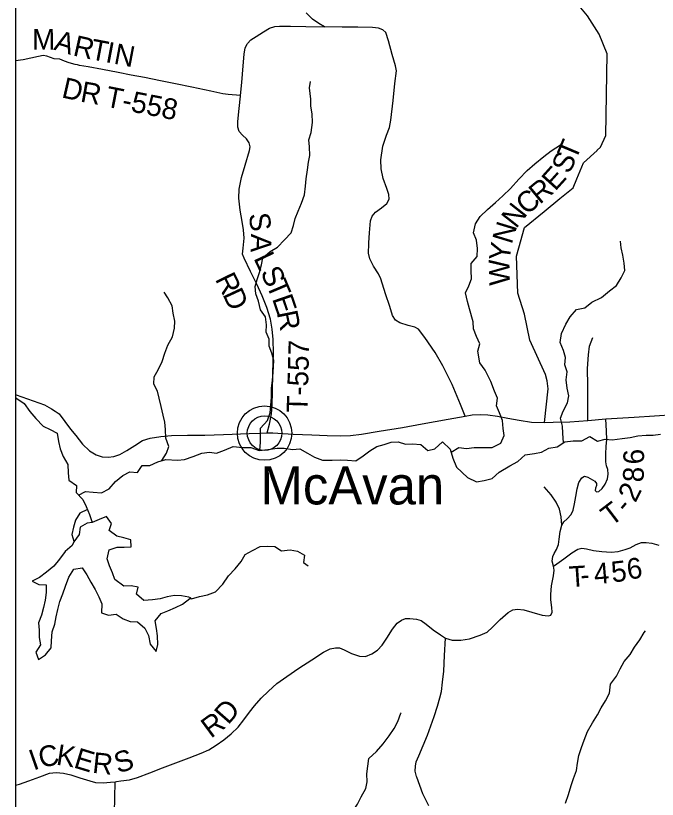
# Model space of a CAD drawing. Extents: x -84548 to 2262448, y -162180 to 525962.
# Drawn here: x 31945 to 41232, y 148023 to 159360 of the extents above; entities that cross this region are included whole.
import ezdxf

# ---------------------------------------------------------------- set-up
doc = ezdxf.new("R2010")
doc.units = 0
for name, color, linetype in [('GM_X_Adjacent_County_Text', 7, 'Continuous'), ('GM_X_County', 7, 'Continuous'), ('GM_X_Interchange_Ramps', 7, 'Continuous'), ('GM_X_Major_Lake_Text', 7, 'Continuous'), ('GM_X_Major_River', 7, 'Continuous'), ('GM_X_Minor_Lake', 7, 'Continuous'), ('GM_X_Minor_River_Text', 7, 'Continuous'), ('GM_X_State_Route', 7, 'Continuous'), ('GM_X_Township_Road', 7, 'Continuous'), ('GM_X_Township_ROW', 7, 'Continuous')]:
    doc.layers.add(name, color=color, linetype=linetype)

msp = doc.modelspace()

# ---------------------------------------------------------------- linework, layer by layer
at = {"layer": 'GM_X_County'}
msp.add_line((31945, 170872), (31945, 134968), dxfattribs=at)
at = {"layer": 'GM_X_Interchange_Ramps'}
for points in [[(34474, 150936), (34450, 150948), (34347, 150966), (34243, 150970), (34136, 150952), (34036, 150922), (33925, 150910), (33799, 150900), (33692, 150992), (33716, 151092), (33616, 151112), (33511, 151106), (33381, 151201), (33348, 151301), (33302, 151403), (33268, 151503), (33298, 151632), (33413, 151670), (33517, 151670), (33618, 151676), (33612, 151778), (33511, 151806), (33411, 151830), (33300, 151910), (33334, 152012), (33260, 152113), (33155, 152069), (33051, 152029)], [(33051, 152029), (32978, 152018), (32878, 151958), (32866, 151852), (32789, 151750)], [(32789, 151750), (32761, 151694), (32661, 151608), (32580, 151499), (32498, 151395), (32393, 151311), (32289, 151233), (32182, 151179), (32283, 151132), (32387, 151124), (32389, 151014), (32371, 150904), (32349, 150800), (32321, 150685), (32277, 150575), (32287, 150469), (32285, 150365), (32303, 150260), (32239, 150150), (32277, 150048), (32377, 150112), (32458, 150212), (32462, 150317), (32476, 150445), (32510, 150557), (32530, 150663), (32556, 150768), (32586, 150884), (32629, 150996), (32667, 151106), (32715, 151239), (32789, 151351), (32908, 151371), (32974, 151271), (33035, 151165), (33097, 151060), (33151, 150952), (33192, 150852), (33186, 150721), (33290, 150685), (33399, 150701), (33501, 150635), (33602, 150595), (33708, 150589), (33817, 150499), (33869, 150393), (33893, 150268), (33980, 150162), (34002, 150262), (33998, 150387), (33984, 150495), (33962, 150603), (34050, 150710), (34150, 150752), (34259, 150798), (34360, 150844), (34466, 150928)], [(34466, 150928), (34490, 150924)], [(34490, 150924), (34474, 150936)]]:
    msp.add_lwpolyline(points, dxfattribs=at)
at = {"layer": 'GM_X_Major_Lake_Text'}
for points in [[(31945, 153877), (31954, 153874), (32362, 153729), (32462, 153674), (32519, 153636), (32573, 153598), (32656, 153489)], [(35326, 153316), (35494, 153322), (35585, 153323), (35668, 153325), (35962, 153307), (36232, 153294), (36454, 153284), (36647, 153279), (36791, 153286), (36951, 153305), (37207, 153347), (37546, 153403), (37830, 153453), (38203, 153523), (38452, 153567), (38552, 153583), (38672, 153592), (38778, 153585), (38920, 153566), (39068, 153539), (39234, 153506), (39410, 153479), (39598, 153475), (39726, 153479), (39968, 153486), (40225, 153503), (40489, 153525), (40899, 153552), (41192, 153570), (41476, 153592)], [(32656, 153489), (32740, 153378), (32814, 153285), (32911, 153163), (33013, 153065), (33110, 153006), (33198, 152979), (33284, 152973), (33366, 152984), (33455, 153012), (33555, 153069), (33668, 153142), (33780, 153213), (33892, 153249), (34045, 153272), (34201, 153285), (34433, 153289), (34683, 153293), (34951, 153302), (35326, 153316)]]:
    msp.add_lwpolyline(points, dxfattribs=at)
at = {"layer": 'GM_X_Major_River'}
for radius in [393, 249]:
    msp.add_circle((35547, 153320), radius, dxfattribs=at)
at = {"layer": 'GM_X_Minor_Lake'}
for points in [[(40363, 157412), (40411, 157457), (40487, 157628), (40506, 158807), (40392, 159092), (40221, 159358), (40126, 159472), (40069, 159529), (40031, 159605), (40069, 159700), (40031, 159852), (39917, 160042), (39936, 160708), (39986, 161675), (39986, 161676)], [(35298, 158950), (35302, 158958), (35349, 159011), (35426, 159060), (35532, 159128), (35619, 159178), (35695, 159204), (35765, 159209), (35923, 159206), (36145, 159203), (36413, 159196)], [(35585, 153323), (35619, 153449), (35646, 153600), (35657, 153730), (35661, 153913), (35669, 154199), (35676, 154480), (35673, 154676), (35660, 154824), (35633, 154970), (35582, 155139), (35513, 155308), (35437, 155475), (35346, 155657), (35252, 155854), (35230, 155909), (35239, 155994), (35252, 156142), (35245, 156260), (35223, 156382), (35195, 156548), (35176, 156722), (35179, 156850), (35216, 157017), (35268, 157196), (35332, 157410), (35339, 157462), (35324, 157518), (35284, 157579), (35229, 157630), (35180, 157685), (35159, 157745), (35161, 157827), (35181, 158016), (35200, 158196), (35201, 158206), (35218, 158395), (35239, 158632), (35253, 158804), (35269, 158893), (35297, 158948), (35298, 158950)], [(32870, 158641), (32841, 158647), (32805, 158653), (32721, 158676), (32654, 158704), (32584, 158729), (32504, 158737), (32450, 158754), (32397, 158773), (32345, 158782), (32275, 158767), (32052, 158720), (31945, 158707)], [(35201, 158206), (35023, 158219), (34945, 158229), (34772, 158268), (34493, 158324), (34259, 158372), (34042, 158416), (33809, 158463), (33618, 158499), (33430, 158536), (33201, 158579), (32994, 158619), (32870, 158641)], [(39227, 155999), (39228, 156000), (39309, 156297), (39594, 156526), (39822, 156716), (40012, 156868), (40069, 157001), (40164, 157229), (40362, 157411), (40363, 157412)], [(39598, 153475), (39651, 153959), (39638, 154079), (39613, 154168), (39385, 154663), (39309, 155043), (39214, 155347), (39195, 155879), (39227, 155999)], [(39729, 151395), (39711, 151467), (39720, 151538), (39737, 151580), (39774, 151635), (39802, 151709), (39813, 151788), (39826, 151896), (39852, 151988), (39879, 152038), (39929, 152081), (39983, 152142), (40012, 152204), (40034, 152297), (40054, 152406), (40074, 152516), (40098, 152607), (40140, 152676), (40178, 152697), (40228, 152684), (40327, 152627), (40354, 152594), (40354, 152564), (40335, 152525), (40334, 152489), (40352, 152470), (40384, 152476), (40433, 152519), (40478, 152582), (40512, 152657), (40519, 152727), (40518, 152793), (40497, 152847), (40485, 152905), (40489, 153019), (40491, 153129), (40501, 153226), (40496, 153348), (40489, 153525)], [(39852, 151988), (39838, 152111), (39816, 152221), (39766, 152320), (39696, 152427), (39595, 152543)], [(39729, 151396), (39742, 151405), (39878, 151503), (39997, 151589), (40083, 151643), (40139, 151654), (40207, 151647), (40308, 151621), (40428, 151606), (40562, 151600), (40666, 151610), (40769, 151635), (40841, 151660), (40926, 151710), (41001, 151737), (41071, 151739), (41153, 151728), (41254, 151698)], [(31945, 148230), (32003, 148242), (32136, 148289), (32297, 148350), (32433, 148399), (32533, 148413), (32639, 148401), (32744, 148375), (32875, 148332), (33017, 148291), (33100, 148268), (33212, 148263), (33320, 148269), (33385, 148277), (33404, 148280), (33467, 148288), (33595, 148306), (33710, 148337), (33885, 148406), (34071, 148476), (34262, 148552), (34456, 148624), (34631, 148690), (34739, 148740), (34846, 148806), (34956, 148882), (35063, 148971), (35167, 149067), (35248, 149171), (35330, 149285), (35400, 149376), (35498, 149484), (35606, 149587), (35727, 149699), (35869, 149798), (36043, 149920), (36230, 150042), (36400, 150153), (36499, 150199), (36574, 150213), (36634, 150212), (36699, 150187), (36808, 150133), (36923, 150092), (37007, 150087), (37100, 150127), (37181, 150181), (37251, 150254), (37319, 150354), (37398, 150484), (37469, 150573), (37530, 150617), (37587, 150638), (37651, 150639), (37745, 150629), (37814, 150608), (37885, 150558), (37990, 150477), (38094, 150401), (38165, 150353), (38263, 150325), (38389, 150323), (38513, 150346), (38670, 150397), (38771, 150441), (38847, 150513), (38959, 150623), (39071, 150727), (39140, 150765), (39210, 150776), (39302, 150762), (39416, 150730), (39567, 150687), (39651, 150675), (39689, 150686), (39708, 150728), (39707, 150798), (39693, 150910), (39689, 150986), (39702, 151113), (39728, 151255), (39740, 151338), (39729, 151395), (39729, 151396)], [(37749, 148353), (37728, 148431), (37731, 148501), (37744, 148563), (37780, 148652), (37841, 148800), (37908, 148953), (37953, 149084), (38002, 149222), (38051, 149369), (38084, 149490), (38107, 149582), (38124, 149717), (38141, 149877), (38150, 150104), (38165, 150353)], [(37927, 147927), (37840, 148101), (37752, 148341), (37749, 148353)], [(33377, 147833), (33382, 148046), (33385, 148277)]]:
    msp.add_lwpolyline(points, dxfattribs=at)
at = {"layer": 'GM_X_Minor_River_Text'}
for points in [[(37058, 156073), (37068, 156220), (37081, 156390), (37107, 156457), (37155, 156519), (37238, 156581), (37318, 156644), (37353, 156704), (37347, 156772), (37319, 156860), (37262, 157002), (37233, 157142), (37229, 157276), (37257, 157471), (37311, 157631), (37356, 157742), (37373, 157850), (37408, 158135), (37435, 158379), (37458, 158562), (37445, 158636), (37396, 158798), (37339, 158998), (37305, 159116), (37259, 159156), (37199, 159178), (37109, 159191), (36899, 159192), (36671, 159195), (36413, 159196), (36331, 159246), (36242, 159308), (36152, 159403)], [(38452, 153567), (38385, 153733), (38263, 154025), (38130, 154295), (38019, 154489), (37866, 154703), (37775, 154825), (37721, 154852), (37625, 154876), (37505, 154914), (37441, 154953), (37400, 155021), (37360, 155153), (37299, 155337), (37228, 155554), (37195, 155626), (37123, 155737), (37072, 155843), (37054, 155925), (37057, 156058), (37058, 156073), (37058, 156073)]]:
    msp.add_lwpolyline(points, dxfattribs=at)
at = {"layer": 'GM_X_State_Route'}
for points in [[(35480, 153072), (35489, 153183), (35491, 153287), (35491, 153394), (35590, 153504), (35628, 153616), (35638, 153718), (35646, 153839), (35648, 153967), (35662, 154087), (35672, 154198), (35682, 154372), (35654, 154478), (35612, 154580), (35612, 154681), (35571, 154781), (35577, 154889), (35559, 155001), (35491, 155104), (35461, 155232), (35421, 155336), (35411, 155442), (35439, 155543), (35473, 155643), (35501, 155753), (35525, 155855), (35630, 155948), (35734, 156012), (35837, 156116), (35935, 156216), (35965, 156322), (35989, 156427), (36036, 156533), (36080, 156647), (36124, 156769), (36142, 156892), (36152, 156998), (36168, 157128), (36184, 157239), (36205, 157339), (36196, 157461), (36188, 157563), (36221, 157670), (36241, 157816), (36237, 157938), (36215, 158052), (36215, 158153), (36200, 158317), (36212, 158409)], [(38247, 153043), (38360, 153111), (38470, 153099), (38581, 153115), (38722, 153113), (38842, 153111), (38969, 153173), (39017, 153287), (39003, 153387), (38991, 153502), (38947, 153612), (38906, 153716), (38919, 153824), (38876, 153929), (38822, 154069), (38740, 154231), (38665, 154338), (38635, 154504), (38663, 154610), (38613, 154717), (38573, 154831), (38565, 154931), (38512, 155121), (38486, 155224), (38454, 155350), (38504, 155450), (38542, 155554), (38536, 155673), (38540, 155773), (38627, 155877), (38629, 155991), (38617, 156112), (38571, 156220), (38599, 156350), (38669, 156455), (38772, 156555), (38888, 156655), (38995, 156755), (39109, 156861), (39226, 156996), (39346, 157120), (39457, 157214), (39588, 157322), (39694, 157403), (39833, 157493)], [(39874, 153182), (39863, 153319), (39859, 153421), (39833, 153536), (39869, 153640), (39932, 153758), (39952, 153860), (39928, 153971), (39912, 154091), (39926, 154205), (39895, 154309), (39901, 154414), (39873, 154516), (39827, 154634), (39845, 154760), (39907, 154895), (39972, 155005), (40062, 155107), (40183, 155133), (40285, 155213), (40422, 155284), (40539, 155380), (40639, 155456), (40708, 155568), (40764, 155673), (40750, 155781), (40732, 155895), (40707, 155999), (40699, 156100)], [(34063, 152924), (34126, 153029), (34160, 153129), (34120, 153249), (34116, 153374), (34102, 153478), (34080, 153582), (34052, 153706), (34020, 153825), (33997, 153929), (33943, 154031), (33951, 154133), (34007, 154234), (34064, 154358), (34106, 154478), (34148, 154592), (34213, 154715), (34243, 154841), (34247, 154941), (34223, 155056), (34208, 155162), (34148, 155278), (34096, 155360)], [(31945, 153837), (31961, 153823), (32070, 153750), (32148, 153632), (32239, 153530), (32345, 153420), (32446, 153372), (32548, 153319), (32564, 153199), (32590, 153091), (32635, 152981), (32699, 152866), (32705, 152744), (32717, 152642), (32826, 152562), (32820, 152460), (32916, 152359), (32968, 152257), (33015, 152145), (33047, 152041), (33051, 152029)], [(32853, 152425), (32956, 152478), (33069, 152468), (33187, 152456), (33298, 152516), (33392, 152620), (33495, 152708), (33600, 152762), (33708, 152750), (33778, 152850), (33887, 152850), (34002, 152907), (34120, 152941), (34287, 152929), (34388, 152939), (34512, 152983), (34641, 153029), (34749, 153043), (34854, 153029), (34968, 153075), (35093, 153129), (35232, 153113), (35348, 153111), (35471, 153071), (35594, 153085), (35730, 153105), (35833, 153101), (35951, 153083), (36056, 153093), (36169, 153029), (36269, 152975), (36386, 152931), (36528, 152929), (36645, 152933), (36750, 152927), (36868, 152921), (36973, 152993), (37073, 153065), (37174, 153127), (37280, 153157), (37381, 153191), (37481, 153195), (37586, 153163), (37688, 153167), (37809, 153157), (37909, 153067), (38014, 153093), (38125, 153195), (38233, 153087), (38273, 152956), (38324, 152828), (38484, 152680), (38613, 152618), (38728, 152634), (38844, 152662), (38945, 152756), (39099, 152848), (39214, 152912), (39321, 153006), (39453, 153027), (39558, 153043), (39664, 153105), (39783, 153123), (39894, 153195), (40012, 153207), (40141, 153211), (40253, 153273), (40366, 153203), (40476, 153235), (40577, 153223), (40724, 153241), (40840, 153257), (40951, 153279), (41071, 153293), (41174, 153293), (41277, 153307)], [(32986, 152215), (32876, 152163), (32810, 152061), (32783, 151958), (32759, 151856), (32785, 151756), (32789, 151750)], [(34490, 150924), (34605, 150958), (34721, 150980), (34836, 151024), (34942, 151136), (35025, 151257), (35121, 151357), (35208, 151463), (35268, 151567), (35373, 151624), (35483, 151680), (35590, 151686), (35694, 151680), (35795, 151620), (35917, 151634), (36026, 151612), (36126, 151553), (36112, 151451), (36181, 151401)], [(39904, 147967), (39948, 148095), (39986, 148223), (40018, 148324), (40061, 148442), (40077, 148548), (40095, 148656), (40133, 148771), (40171, 148877), (40221, 149005), (40296, 149129), (40368, 149246), (40420, 149348), (40483, 149450), (40539, 149558), (40553, 149687), (40640, 149803), (40694, 149913), (40750, 150017), (40839, 150118), (40901, 150222), (40977, 150330), (41042, 150438), (41060, 150462)], [(36521, 147066), (36519, 147173), (36527, 147280), (36509, 147430), (36545, 147538), (36629, 147644), (36694, 147749), (36822, 147841), (36891, 147953), (36947, 148061), (37011, 148178), (37033, 148278), (37027, 148392), (37041, 148502), (37059, 148611), (37168, 148713), (37266, 148827), (37351, 148941), (37423, 149048), (37478, 149148), (37522, 149268), (37524, 149274)]]:
    msp.add_lwpolyline(points, dxfattribs=at)
at = {"layer": 'GM_X_Township_ROW'}
msp.add_lwpolyline([(40225, 153503), (40226, 153773), (40227, 154010), (40222, 154256), (40236, 154455), (40251, 154581), (40301, 154706)], dxfattribs=at)

# ---------------------------------------------------------------- texts
at = {"layer": 'GM_X_Adjacent_County_Text'}
msp.add_text('McAvan', height=550, rotation=0, dxfattribs=at).set_placement((35490, 152289))
at = {"layer": 'GM_X_Township_Road'}
for s, rotation, p in [('M', 0.2333, (32183, 158866)), ('A', 342.9532, (32485, 158871)), ('R', 347.4548, (32762, 158787)), ('T', 349.2826, (33013, 158732)), ('I', 349.2672, (33233, 158690)), ('N', 349.2655, (33354, 158667)), ('D', 347.2175, (32598, 158180)), ('R', 349.8245, (32870, 158118)), ('T-558', 348.8534, (33229, 158048)), ('T', 67.2184, (40050, 157254)), ('S', 64.5291, (39957, 157057)), ('E', 47.9617, (39754, 156812)), ('R', 39.4593, (39529, 156622)), ('C', 39.7836, (39340, 156465)), ('N', 51.6736, (39187, 156269)), ('S', 277.8647, (35317, 156489)), ('N', 73.0783, (39124, 156043)), ('A', 268.5792, (35351, 156206)), ('Y', 82.0479, (39090, 155794)), ('L', 295.2472, (35384, 155852)), ('W', 91.555, (39100, 155459)), ('S', 295.7986, (35481, 155647)), ('R', 296.1112, (34827, 155550)), ('T', 293.0104, (35567, 155468)), ('D', 294.9431, (34935, 155330)), ('E', 288.9743, (35653, 155267)), ('R', 281.561, (35723, 155064)), ('T-557', 88.3276, (36166, 153615)), ('6', 91.8381, (41044, 152873)), ('8', 88.3779, (41033, 152607)), ('2', 63.2385, (40915, 152304)), ('T', 37.3053, (40562, 151962)), ('-', 49.436, (40791, 152145)), ('5', 6.2983, (40580, 151160)), ('6', 7.4922, (40809, 151201)), ('T', 3.6667, (39963, 151092)), ('4', 4.5891, (40325, 151135)), ('-', 3.8952, (40126, 151120)), ('D', 48.9937, (35021, 149091)), ('R', 36.4655, (34771, 148897)), ('I', 19.3088, (32203, 148437)), ('C', 12.0991, (32310, 148475)), ('K', 350.9191, (32521, 148526)), ('E', 342.9408, (32771, 148487)), ('R', 353.8481, (33047, 148408)), ('S', 17.5896, (33426, 148395))]:
    msp.add_text(s, height=300, rotation=rotation, dxfattribs=at).set_placement(p)

doc.saveas('drawing.dxf')
